Omron CX-Programmer project TrafficLights (CX-Programmer 6.00)
; Project containing program which controls a typical traffic light sequence - useful to illustrate use of symbols (including NUMBER data-types), and basic ladder constructs.

# PLC TrafficController: CJ1M CPU21
; The IO table has been set to include the traffic lights on an output card, so that the 'Q' prefixes will appear.
I/O table (CPU CJ1M-CPU21): rack 0 slot 0 CJ1W-ETN21(ETN21Mode); rack 0 slot 1 CJ1W-CLK21

## Global symbols (name address type ; comment)
T1000 BOOL  ; 1000

## Program Traffic_Lights (cyclic task 0)
; Example program to control UK traffic lights / Note that the I/O table has been set to include the traffic lights as outputs, and so the addresses appear with 'Q' prefixes.
Local symbols
AmberLight 0.01 BOOL  ; Prepare to go/stop
AmberLightTimer 2 NUMBER  ; Timer for the amber light period
AmberOnlyTimer 4 NUMBER  ; Timer for the amber only period
AmberOnlyTimerDone T0004 BOOL
AmberTimerDone T0002 BOOL
GreenLight 0.02 BOOL  ; Go
GreenLightTimer 3 NUMBER  ; Timer for the green light period
GreenTimerDone T0003 BOOL
RedLight 0.00 BOOL  ; Stop
RedLightTimer 1 NUMBER  ; Timer for the red light period
RedTimerDone T0001 BOOL
Reset 11.00 BOOL  ; Resets Timers/Counters
TimeInterval 48 NUMBER  ; Speed at which the sequence works (ticks)
op 0.04 BOOL
var_11 4.00 BOOL

### Section Section1
; The only section necessary in such a small program

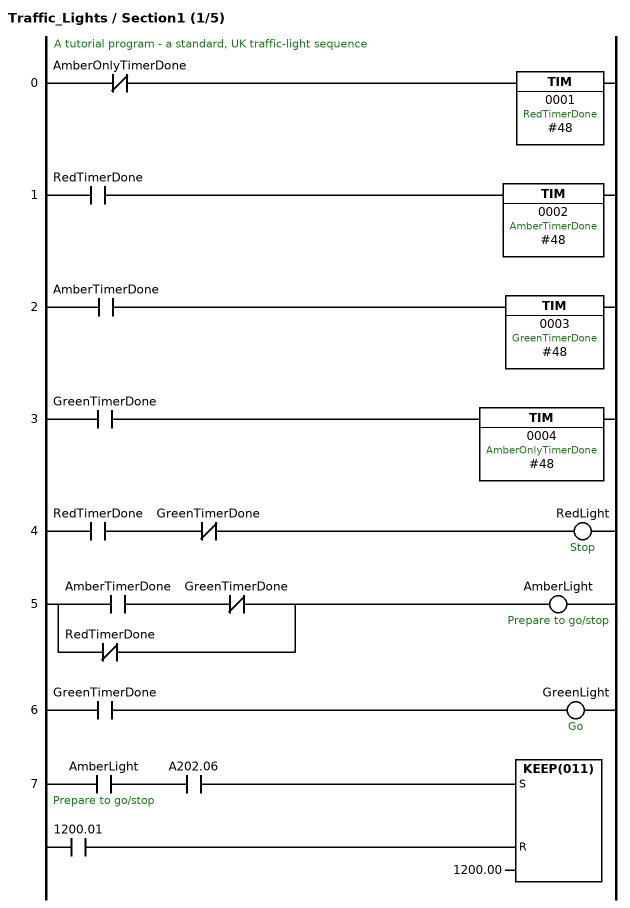
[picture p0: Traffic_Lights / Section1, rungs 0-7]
; rung 0: A tutorial program - a standard, UK traffic-light sequence
LDNOT AmberOnlyTimerDone
TIM 0001 #48  ; RedTimerDone  // Red light on only
; rung 1
LD RedTimerDone
TIM 0002 #48  ; AmberTimerDone  // Red and amber lights on together
; rung 2
LD AmberTimerDone
TIM 0003 #48  ; GreenTimerDone  // Green light on only
; rung 3
LD GreenTimerDone
TIM 0004 #48  ; AmberOnlyTimerDone  // Amber light on only
; rung 4
LD RedTimerDone
ANDNOT GreenTimerDone
OUT RedLight  ; Stop
; rung 5
LD AmberTimerDone
ANDNOT GreenTimerDone
ORNOT RedTimerDone
OUT AmberLight  ; Prepare to go/stop
; rung 6
LD GreenTimerDone
OUT GreenLight  ; Go
; rung 7
LD AmberLight  ; Prepare to go/stop
AND A202.06
LD 1200.01
KEEP(011) 1200.00

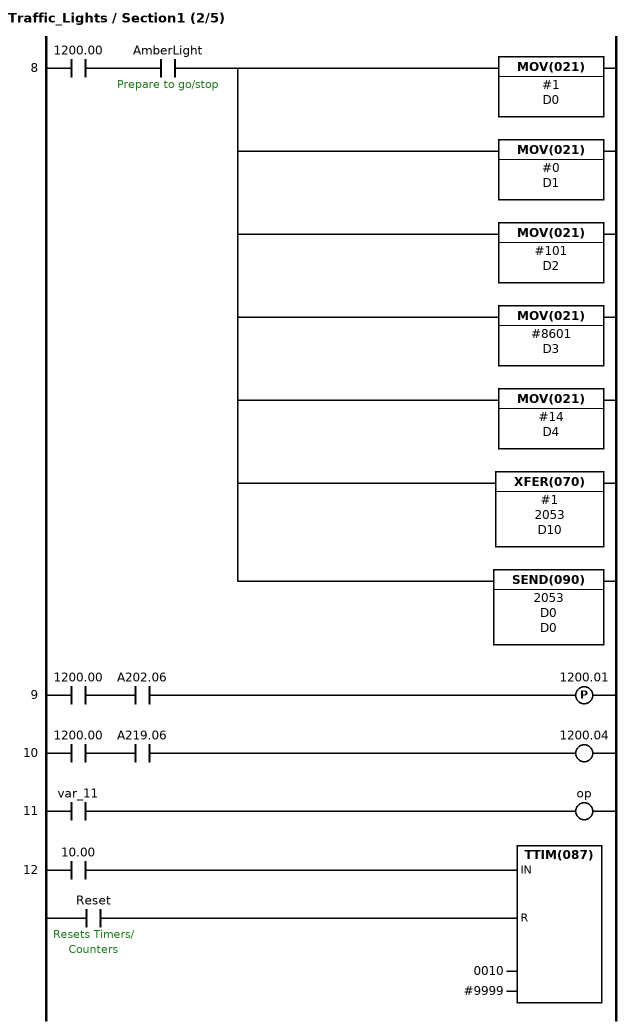
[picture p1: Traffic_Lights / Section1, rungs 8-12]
; rung 8
LD 1200.00
AND AmberLight  ; Prepare to go/stop
MOV(021) #1 D0
MOV(021) #0 D1
MOV(021) #101 D2
MOV(021) #8601 D3
MOV(021) #14 D4
XFER(070) #1 2053 D10
SEND(090) 2053 D0 D0
; rung 9
LD 1200.00
AND A202.06
DIFU(013) 1200.01
; rung 10
LD 1200.00
AND A219.06
OUT 1200.04
; rung 11
LD var_11
OUT op
; rung 12
LD 10.00
LD Reset  ; Resets Timers/Counters
TTIM(087) 0010 #9999

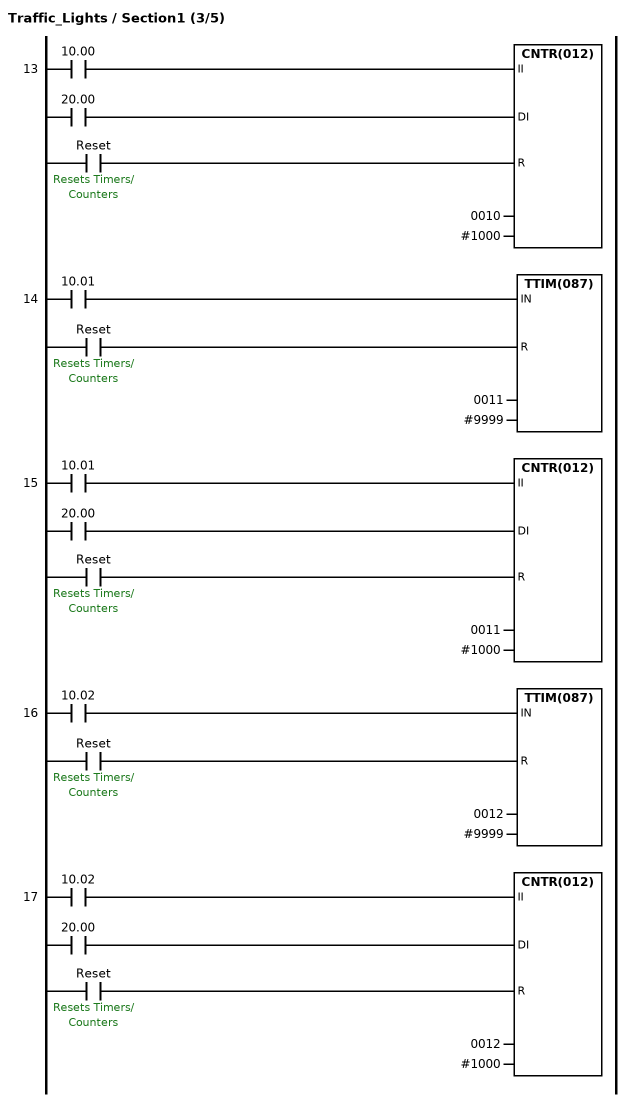
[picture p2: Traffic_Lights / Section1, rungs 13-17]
; rung 13
LD 10.00
LD 20.00
LD Reset  ; Resets Timers/Counters
CNTR(012) 0010 #1000
; rung 14
LD 10.01
LD Reset  ; Resets Timers/Counters
TTIM(087) 0011 #9999
; rung 15
LD 10.01
LD 20.00
LD Reset  ; Resets Timers/Counters
CNTR(012) 0011 #1000
; rung 16
LD 10.02
LD Reset  ; Resets Timers/Counters
TTIM(087) 0012 #9999
; rung 17
LD 10.02
LD 20.00
LD Reset  ; Resets Timers/Counters
CNTR(012) 0012 #1000

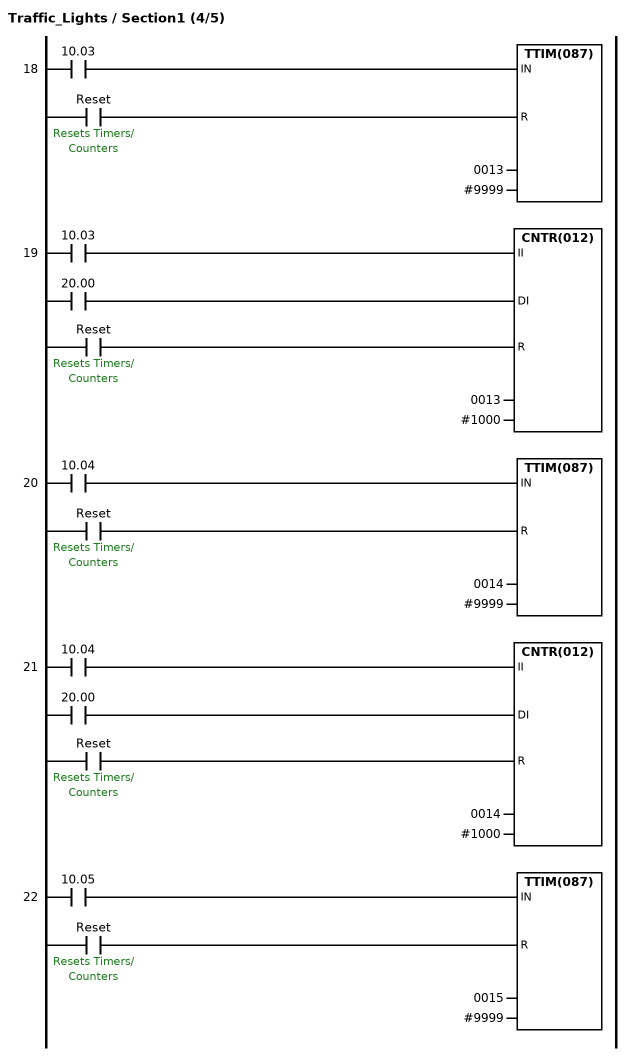
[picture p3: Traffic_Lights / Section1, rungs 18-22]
; rung 18
LD 10.03
LD Reset  ; Resets Timers/Counters
TTIM(087) 0013 #9999
; rung 19
LD 10.03
LD 20.00
LD Reset  ; Resets Timers/Counters
CNTR(012) 0013 #1000
; rung 20
LD 10.04
LD Reset  ; Resets Timers/Counters
TTIM(087) 0014 #9999
; rung 21
LD 10.04
LD 20.00
LD Reset  ; Resets Timers/Counters
CNTR(012) 0014 #1000
; rung 22
LD 10.05
LD Reset  ; Resets Timers/Counters
TTIM(087) 0015 #9999

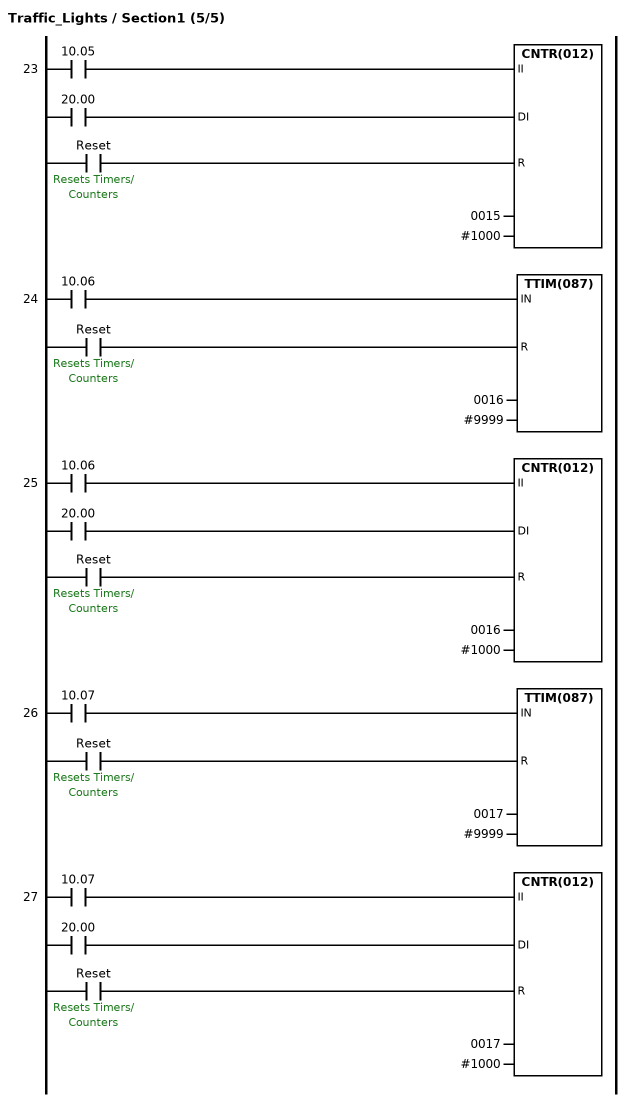
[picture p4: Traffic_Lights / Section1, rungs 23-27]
; rung 23
LD 10.05
LD 20.00
LD Reset  ; Resets Timers/Counters
CNTR(012) 0015 #1000
; rung 24
LD 10.06
LD Reset  ; Resets Timers/Counters
TTIM(087) 0016 #9999
; rung 25
LD 10.06
LD 20.00
LD Reset  ; Resets Timers/Counters
CNTR(012) 0016 #1000
; rung 26
LD 10.07
LD Reset  ; Resets Timers/Counters
TTIM(087) 0017 #9999
; rung 27
LD 10.07
LD 20.00
LD Reset  ; Resets Timers/Counters
CNTR(012) 0017 #1000

### Section END
; rung 0
END(001)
